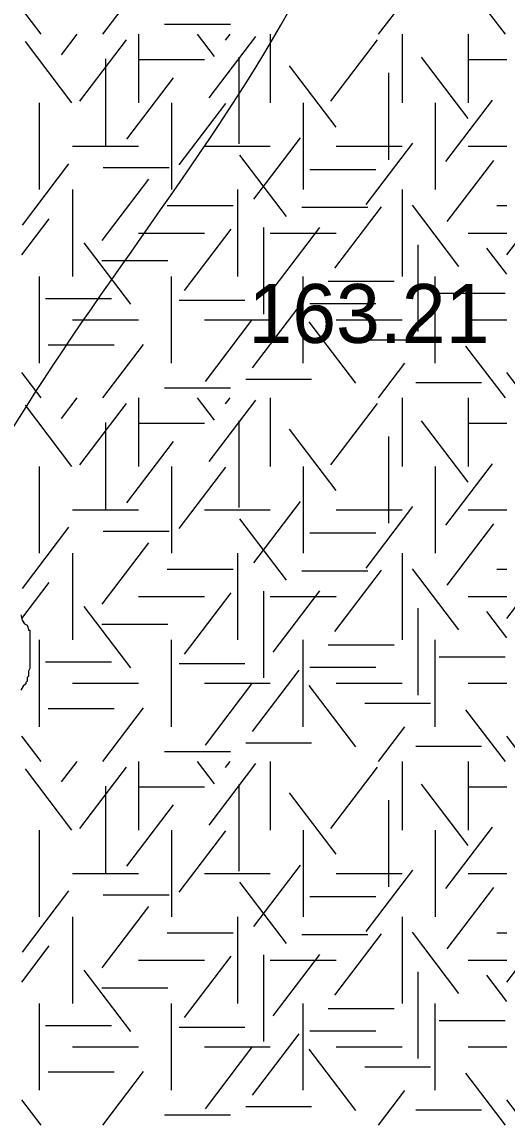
# Model space of a CAD drawing. Extents: x 419101 to 420177, y 4451541 to 4452254.
# Drawn here: x 419913.42 to 419923.3, y 4451647.89 to 4451670.27 of the extents above; entities that cross this region are included whole.
import ezdxf

# ---------------------------------------------------------------- set-up
doc = ezdxf.new("R2010")
doc.units = 0
for name, color, linetype in [('3_HALİHAZIR', 7, 'Continuous'), ('Level 3', 7, 'Continuous'), ('Level 41', 7, 'Continuous')]:
    doc.layers.add(name, color=color, linetype=linetype)

msp = doc.modelspace()

# ---------------------------------------------------------------- linework, layer by layer
at = {"layer": '3_HALİHAZIR'}
for points in [[(419903.245, 4451652.867), (419908.888, 4451656.212), (419913.846, 4451662.961), (419919.769, 4451672.327), (419922.386, 4451685.274), (419924.026, 4451697.625)], [(419846.731, 4451613.4), (419846.734, 4451613.401), (419851.514, 4451616.401), (419885.634, 4451630.941), (419888.984, 4451632.301), (419889.844, 4451632.681), (419890.744, 4451632.961), (419895.264, 4451633.531), (419919.823, 4451636.751), (419931.005, 4451651.381), (419931.911, 4451652.564)]]:
    msp.add_spline(points, degree=3, dxfattribs=at)
at = {"layer": 'Level 3'}
msp.add_lwpolyline([(419913.392, 4451658.186), (419913.418, 4451658.082), (419913.47, 4451658.004), (419913.522, 4451657.978), (419913.548, 4451657.9), (419913.548, 4451657.874), (419913.574, 4451657.874), (419913.574, 4451657.848), (419913.574, 4451657.822), (419913.574, 4451657.77), (419913.574, 4451657.667), (419913.574, 4451657.615), (419913.574, 4451657.537), (419913.574, 4451657.459), (419913.574, 4451657.381), (419913.574, 4451657.303), (419913.574, 4451657.225), (419913.574, 4451657.173), (419913.574, 4451657.095), (419913.548, 4451657.043), (419913.548, 4451656.939), (419913.522, 4451656.913), (419913.522, 4451656.836), (419913.496, 4451656.81), (419913.496, 4451656.784), (419913.444, 4451656.732), (419913.392, 4451656.654)], dxfattribs=at)
at = {"layer": 'Level 41'}
for p, q in [((419915.061, 4451670.018), (419915.89, 4451671.109)), ((419923.264, 4451670.018), (419922.462, 4451671.074)), ((419913.808, 4451670.018), (419913.414, 4451670.536)), ((419920.681, 4451670.018), (419921.218, 4451670.724)), ((419916.323, 4451670.224), (419917.666, 4451670.224)), ((419914.435, 4451668.62), (419913.486, 4451669.87)), ((419914.224, 4451669.601), (419914.541, 4451670.018)), ((419914.595, 4451668.655), (419915.544, 4451669.905)), ((419915.79, 4451670.018), (419915.79, 4451668.62)), ((419917.339, 4451669.566), (419916.995, 4451670.018)), ((419917.232, 4451668.724), (419918.182, 4451669.974)), ((419917.565, 4451669.898), (419917.656, 4451670.018)), ((419918.476, 4451670.018), (419918.476, 4451668.62)), ((419919.709, 4451668.655), (419920.658, 4451669.905)), ((419921.162, 4451670.018), (419921.162, 4451668.62)), ((419922.505, 4451670.018), (419922.505, 4451668.62)), ((419922.505, 4451670.018), (419922.505, 4451668.62)), ((419915.115, 4451669.516), (419915.115, 4451667.749)), ((419915.79, 4451669.504), (419917.133, 4451669.504)), ((419917.832, 4451669.551), (419917.832, 4451667.784)), ((419922.506, 4451668.304), (419921.557, 4451669.553)), ((419922.505, 4451669.504), (419923.293, 4451669.504)), ((419919.816, 4451668.129), (419918.867, 4451669.378)), ((419920.88, 4451669.23), (419920.88, 4451667.463)), ((419915.555, 4451667.883), (419916.504, 4451669.133)), ((419913.776, 4451666.853), (419913.776, 4451668.62)), ((419916.462, 4451668.62), (419916.462, 4451666.853)), ((419916.621, 4451667.358), (419917.57, 4451668.608)), ((419919.148, 4451668.62), (419919.148, 4451666.853)), ((419921.834, 4451668.62), (419921.834, 4451666.853)), ((419921.834, 4451668.62), (419921.834, 4451666.853)), ((419922.054, 4451667.427), (419923.003, 4451668.677)), ((419918.138, 4451666.657), (419919.089, 4451667.906)), ((419914.447, 4451667.736), (419915.79, 4451667.736)), ((419917.133, 4451667.736), (419918.476, 4451667.736)), ((419919.819, 4451667.736), (419921.162, 4451667.736)), ((419920.429, 4451666.552), (419921.378, 4451667.802)), ((419922.505, 4451667.736), (419923.293, 4451667.736)), ((419918.804, 4451666.307), (419917.854, 4451667.556)), ((419922.08, 4451666.201), (419923.03, 4451667.45)), ((419913.424, 4451666.132), (419914.373, 4451667.381)), ((419915.071, 4451667.302), (419916.414, 4451667.302)), ((419919.279, 4451667.266), (419920.622, 4451667.266)), ((419915.049, 4451665.815), (419915.998, 4451667.065)), ((419914.447, 4451666.853), (419914.447, 4451665.086)), ((419917.805, 4451666.853), (419917.805, 4451665.086)), ((419921.162, 4451666.853), (419921.162, 4451665.086)), ((419916.377, 4451666.529), (419917.72, 4451666.529)), ((419919.119, 4451666.496), (419920.462, 4451666.496)), ((419919.789, 4451665.255), (419920.739, 4451666.505)), ((419922.319, 4451665.289), (419921.37, 4451666.538)), ((419923.089, 4451666.529), (419923.293, 4451666.529)), ((419913.414, 4451665.523), (419913.973, 4451666.259)), ((419916.726, 4451664.799), (419917.676, 4451666.049)), ((419918.337, 4451666.081), (419918.337, 4451664.313)), ((419918.537, 4451664.835), (419919.486, 4451666.084)), ((419923.293, 4451665.523), (419923.852, 4451666.259)), ((419915.79, 4451665.969), (419917.133, 4451665.969)), ((419918.476, 4451665.969), (419919.819, 4451665.969)), ((419922.505, 4451665.969), (419923.293, 4451665.969)), ((419915.634, 4451664.518), (419914.685, 4451665.768)), ((419921.48, 4451665.731), (419921.48, 4451663.963)), ((419923.293, 4451665.129), (419922.887, 4451665.663)), ((419915.044, 4451665.409), (419916.387, 4451665.409)), ((419913.776, 4451663.318), (419913.776, 4451665.086)), ((419916.462, 4451663.318), (419916.462, 4451665.086)), ((419919.148, 4451663.318), (419919.148, 4451665.086)), ((419919.653, 4451664.988), (419920.996, 4451664.988)), ((419921.834, 4451663.318), (419921.834, 4451665.086)), ((419921.916, 4451664.743), (419923.259, 4451664.743)), ((419913.899, 4451664.637), (419915.242, 4451664.637)), ((419916.616, 4451664.603), (419917.959, 4451664.603)), ((419919.279, 4451664.532), (419920.622, 4451664.532)), ((419918.112, 4451663.221), (419919.061, 4451664.471)), ((419914.447, 4451664.202), (419915.79, 4451664.202)), ((419917.133, 4451664.202), (419918.476, 4451664.202)), ((419917.152, 4451662.942), (419918.101, 4451664.191)), ((419920.215, 4451662.907), (419919.265, 4451664.156)), ((419919.819, 4451664.202), (419921.162, 4451664.202)), ((419922.505, 4451664.202), (419923.293, 4451664.202)), ((419913.953, 4451663.691), (419915.295, 4451663.691)), ((419915.061, 4451662.609), (419915.89, 4451663.7)), ((419920.398, 4451663.795), (419921.741, 4451663.795)), ((419923.264, 4451662.609), (419922.462, 4451663.665)), ((419920.681, 4451662.609), (419921.218, 4451663.315)), ((419913.808, 4451662.609), (419913.414, 4451663.127)), ((419917.975, 4451662.99), (419919.318, 4451662.99)), ((419921.437, 4451662.921), (419922.78, 4451662.921)), ((419923.687, 4451662.609), (419923.293, 4451663.127)), ((419916.323, 4451662.815), (419917.666, 4451662.815)), ((419914.224, 4451662.192), (419914.541, 4451662.609)), ((419914.595, 4451661.246), (419915.544, 4451662.496)), ((419915.79, 4451662.609), (419915.79, 4451661.211)), ((419917.339, 4451662.157), (419916.995, 4451662.609)), ((419917.232, 4451661.315), (419918.182, 4451662.565)), ((419917.565, 4451662.489), (419917.656, 4451662.609)), ((419918.476, 4451662.609), (419918.476, 4451661.211)), ((419919.709, 4451661.246), (419920.658, 4451662.496)), ((419921.162, 4451662.609), (419921.162, 4451661.211)), ((419922.505, 4451662.609), (419922.505, 4451661.211)), ((419922.505, 4451662.609), (419922.505, 4451661.211)), ((419914.435, 4451661.211), (419913.486, 4451662.461)), ((419915.115, 4451662.107), (419915.115, 4451660.34)), ((419915.79, 4451662.095), (419917.133, 4451662.095)), ((419917.832, 4451662.142), (419917.832, 4451660.375)), ((419922.506, 4451660.895), (419921.557, 4451662.144)), ((419922.505, 4451662.095), (419923.293, 4451662.095)), ((419919.816, 4451660.72), (419918.867, 4451661.969)), ((419920.88, 4451661.821), (419920.88, 4451660.054)), ((419915.555, 4451660.474), (419916.504, 4451661.724)), ((419913.776, 4451659.444), (419913.776, 4451661.211)), ((419916.462, 4451661.211), (419916.462, 4451659.444)), ((419916.621, 4451659.949), (419917.57, 4451661.199)), ((419919.148, 4451661.211), (419919.148, 4451659.444)), ((419921.834, 4451661.211), (419921.834, 4451659.444)), ((419921.834, 4451661.211), (419921.834, 4451659.444)), ((419922.054, 4451660.018), (419923.003, 4451661.268)), ((419918.138, 4451659.248), (419919.089, 4451660.497)), ((419914.447, 4451660.327), (419915.79, 4451660.327)), ((419917.133, 4451660.327), (419918.476, 4451660.327)), ((419919.819, 4451660.327), (419921.162, 4451660.327)), ((419920.429, 4451659.143), (419921.378, 4451660.393)), ((419922.505, 4451660.327), (419923.293, 4451660.327)), ((419918.804, 4451658.898), (419917.854, 4451660.147)), ((419922.08, 4451658.792), (419923.03, 4451660.041)), ((419913.424, 4451658.723), (419914.373, 4451659.972)), ((419915.071, 4451659.893), (419916.414, 4451659.893)), ((419919.279, 4451659.857), (419920.622, 4451659.857)), ((419915.049, 4451658.406), (419915.998, 4451659.656)), ((419914.447, 4451659.444), (419914.447, 4451657.677)), ((419917.805, 4451659.444), (419917.805, 4451657.677)), ((419921.162, 4451659.444), (419921.162, 4451657.677)), ((419916.377, 4451659.12), (419917.72, 4451659.12)), ((419922.319, 4451657.88), (419921.37, 4451659.129)), ((419923.089, 4451659.12), (419923.293, 4451659.12)), ((419919.119, 4451659.087), (419920.462, 4451659.087)), ((419919.789, 4451657.846), (419920.739, 4451659.096)), ((419913.414, 4451658.114), (419913.973, 4451658.85)), ((419918.337, 4451658.672), (419918.337, 4451656.904)), ((419918.537, 4451657.426), (419919.486, 4451658.675)), ((419923.293, 4451658.114), (419923.852, 4451658.85)), ((419915.79, 4451658.56), (419917.133, 4451658.56)), ((419916.726, 4451657.39), (419917.676, 4451658.64)), ((419918.476, 4451658.56), (419919.819, 4451658.56)), ((419922.505, 4451658.56), (419923.293, 4451658.56)), ((419915.634, 4451657.109), (419914.685, 4451658.359)), ((419921.48, 4451658.322), (419921.48, 4451656.554)), ((419923.293, 4451657.72), (419922.887, 4451658.254)), ((419915.044, 4451658), (419916.387, 4451658)), ((419913.776, 4451655.909), (419913.776, 4451657.677)), ((419916.462, 4451655.909), (419916.462, 4451657.677)), ((419919.148, 4451655.909), (419919.148, 4451657.677)), ((419919.653, 4451657.579), (419920.996, 4451657.579)), ((419921.834, 4451655.909), (419921.834, 4451657.677)), ((419921.916, 4451657.334), (419923.259, 4451657.334)), ((419913.899, 4451657.228), (419915.242, 4451657.228)), ((419916.616, 4451657.194), (419917.959, 4451657.194)), ((419919.279, 4451657.123), (419920.622, 4451657.123)), ((419918.112, 4451655.812), (419919.061, 4451657.062)), ((419914.447, 4451656.793), (419915.79, 4451656.793)), ((419917.133, 4451656.793), (419918.476, 4451656.793)), ((419917.152, 4451655.533), (419918.101, 4451656.782)), ((419920.215, 4451655.498), (419919.265, 4451656.747)), ((419919.819, 4451656.793), (419921.162, 4451656.793)), ((419922.505, 4451656.793), (419923.293, 4451656.793)), ((419913.953, 4451656.282), (419915.295, 4451656.282)), ((419915.061, 4451655.2), (419915.89, 4451656.291)), ((419920.398, 4451656.386), (419921.741, 4451656.386)), ((419923.264, 4451655.2), (419922.462, 4451656.256)), ((419920.681, 4451655.2), (419921.218, 4451655.906)), ((419913.808, 4451655.2), (419913.414, 4451655.718)), ((419917.975, 4451655.581), (419919.318, 4451655.581)), ((419923.687, 4451655.2), (419923.293, 4451655.718)), ((419916.323, 4451655.406), (419917.666, 4451655.406)), ((419921.437, 4451655.512), (419922.78, 4451655.512)), ((419914.224, 4451654.783), (419914.541, 4451655.2)), ((419914.595, 4451653.837), (419915.544, 4451655.087)), ((419915.79, 4451655.2), (419915.79, 4451653.802)), ((419917.339, 4451654.748), (419916.995, 4451655.2)), ((419917.232, 4451653.906), (419918.182, 4451655.156)), ((419917.565, 4451655.08), (419917.656, 4451655.2)), ((419918.476, 4451655.2), (419918.476, 4451653.802)), ((419919.709, 4451653.837), (419920.658, 4451655.087)), ((419921.162, 4451655.2), (419921.162, 4451653.802)), ((419922.505, 4451655.2), (419922.505, 4451653.802)), ((419922.505, 4451655.2), (419922.505, 4451653.802)), ((419914.435, 4451653.802), (419913.486, 4451655.052)), ((419915.115, 4451654.698), (419915.115, 4451652.931)), ((419915.79, 4451654.686), (419917.133, 4451654.686)), ((419917.832, 4451654.733), (419917.832, 4451652.966)), ((419922.506, 4451653.486), (419921.557, 4451654.735)), ((419922.505, 4451654.686), (419923.293, 4451654.686)), ((419919.816, 4451653.311), (419918.867, 4451654.56)), ((419920.88, 4451654.412), (419920.88, 4451652.645)), ((419915.555, 4451653.065), (419916.504, 4451654.315)), ((419913.776, 4451652.035), (419913.776, 4451653.802)), ((419916.462, 4451653.802), (419916.462, 4451652.035)), ((419916.621, 4451652.54), (419917.57, 4451653.79)), ((419919.148, 4451653.802), (419919.148, 4451652.035)), ((419921.834, 4451653.802), (419921.834, 4451652.035)), ((419921.834, 4451653.802), (419921.834, 4451652.035)), ((419922.054, 4451652.609), (419923.003, 4451653.859)), ((419918.138, 4451651.839), (419919.089, 4451653.088)), ((419914.447, 4451652.918), (419915.79, 4451652.918)), ((419917.133, 4451652.918), (419918.476, 4451652.918)), ((419919.819, 4451652.918), (419921.162, 4451652.918)), ((419920.429, 4451651.734), (419921.378, 4451652.984)), ((419922.505, 4451652.918), (419923.293, 4451652.918)), ((419918.804, 4451651.489), (419917.854, 4451652.738)), ((419922.08, 4451651.383), (419923.03, 4451652.632)), ((419913.424, 4451651.314), (419914.373, 4451652.563)), ((419915.071, 4451652.484), (419916.414, 4451652.484)), ((419919.279, 4451652.448), (419920.622, 4451652.448)), ((419915.049, 4451650.997), (419915.998, 4451652.247)), ((419914.447, 4451652.035), (419914.447, 4451650.268)), ((419917.805, 4451652.035), (419917.805, 4451650.268)), ((419921.162, 4451652.035), (419921.162, 4451650.268)), ((419916.377, 4451651.711), (419917.72, 4451651.711)), ((419919.119, 4451651.678), (419920.462, 4451651.678)), ((419919.789, 4451650.437), (419920.739, 4451651.687)), ((419922.319, 4451650.471), (419921.37, 4451651.72)), ((419923.089, 4451651.711), (419923.293, 4451651.711)), ((419913.414, 4451650.705), (419913.973, 4451651.441)), ((419923.293, 4451650.705), (419923.852, 4451651.441)), ((419915.79, 4451651.151), (419917.133, 4451651.151)), ((419916.726, 4451649.981), (419917.676, 4451651.231)), ((419918.337, 4451651.263), (419918.337, 4451649.495)), ((419918.476, 4451651.151), (419919.819, 4451651.151)), ((419918.537, 4451650.017), (419919.486, 4451651.266)), ((419922.505, 4451651.151), (419923.293, 4451651.151)), ((419915.634, 4451649.7), (419914.685, 4451650.95)), ((419921.48, 4451650.913), (419921.48, 4451649.145)), ((419923.293, 4451650.311), (419922.887, 4451650.845)), ((419915.044, 4451650.591), (419916.387, 4451650.591)), ((419913.776, 4451648.5), (419913.776, 4451650.268)), ((419916.462, 4451648.5), (419916.462, 4451650.268)), ((419919.148, 4451648.5), (419919.148, 4451650.268)), ((419919.653, 4451650.17), (419920.996, 4451650.17)), ((419921.834, 4451648.5), (419921.834, 4451650.268)), ((419913.899, 4451649.819), (419915.242, 4451649.819)), ((419916.616, 4451649.785), (419917.959, 4451649.785)), ((419919.279, 4451649.714), (419920.622, 4451649.714)), ((419921.916, 4451649.925), (419923.259, 4451649.925)), ((419918.112, 4451648.403), (419919.061, 4451649.653)), ((419914.447, 4451649.384), (419915.79, 4451649.384)), ((419917.133, 4451649.384), (419918.476, 4451649.384)), ((419917.152, 4451648.124), (419918.101, 4451649.373)), ((419920.215, 4451648.089), (419919.265, 4451649.338)), ((419919.819, 4451649.384), (419921.162, 4451649.384)), ((419922.505, 4451649.384), (419923.293, 4451649.384)), ((419913.953, 4451648.873), (419915.295, 4451648.873)), ((419915.061, 4451647.791), (419915.89, 4451648.882)), ((419920.398, 4451648.977), (419921.741, 4451648.977)), ((419923.264, 4451647.791), (419922.462, 4451648.847)), ((419920.681, 4451647.791), (419921.218, 4451648.497)), ((419913.808, 4451647.791), (419913.414, 4451648.309)), ((419917.975, 4451648.172), (419919.318, 4451648.172)), ((419923.687, 4451647.791), (419923.293, 4451648.309)), ((419916.323, 4451647.997), (419917.666, 4451647.997)), ((419921.437, 4451648.103), (419922.78, 4451648.103))]:
    msp.add_line(p, q, dxfattribs=at)

# ---------------------------------------------------------------- texts
at = {"layer": '3_HALİHAZIR'}
msp.add_text('163.21 ', height=1.2, rotation=359.9971, dxfattribs=at).set_placement((419918.03, 4451663.73))

doc.saveas('drawing.dxf')
